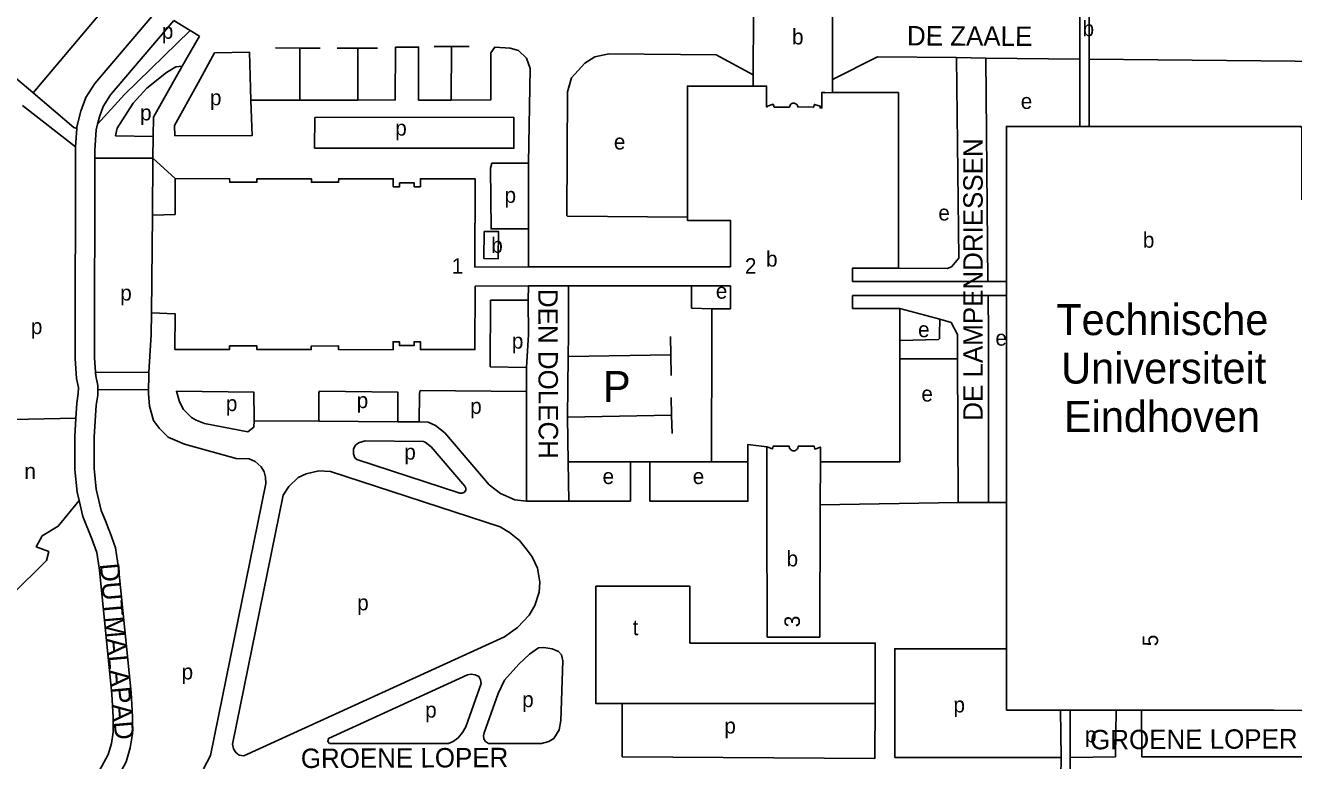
# Model space of a CAD drawing. Extents: x 161494 to 163033, y 383688 to 384862.
# Drawn here: x 161678.1 to 162005.1, y 384190.1 to 384379.7 of the extents above; entities that cross this region are included whole.
import ezdxf

# ---------------------------------------------------------------- set-up
doc = ezdxf.new("R2010")
doc.units = 0
for name, color, linetype in [('BLT_Basislijn', 7, 'Continuous'), ('BLT_Bebouwing', 7, 'Continuous'), ('BLT_Bebouwing_beschrifting', 7, 'Continuous'), ('BLT_Centroide', 7, 'Continuous'), ('BLT_Huisnummer', 7, 'Continuous'), ('BLT_Huisnummer_reeks', 7, 'Continuous'), ('BLT_Onderdoorgang_en_onderverdeling', 7, 'Continuous'), ('BLT_Onderverdeling_panden', 7, 'Continuous'), ('BLT_Straatnaam', 7, 'Continuous'), ('BLT_Tekst_parkeren', 7, 'Continuous'), ('BLT_Vlakafsluiter', 7, 'Continuous')]:
    doc.layers.add(name, color=color, linetype=linetype)

msp = doc.modelspace()

# ---------------------------------------------------------------- linework, layer by layer
at = {"layer": 'BLT_Basislijn'}
for p, q in [((161716.45, 384405.5), (161680.09, 384362.34)), ((161720.58, 384378.35), (161716.39, 384380.97)), ((161722.94, 384376.88), (161718.53, 384369.19)), ((161722.94, 384376.88), (161720.58, 384378.35)), ((161742.6, 384373.87), (161748.86, 384373.84)), ((161748.81, 384360.44), (161748.86, 384373.84)), ((161748.86, 384373.84), (161754.12, 384373.82)), ((161758.47, 384373.83), (161763.83, 384373.84)), ((161763.77, 384360.45), (161763.83, 384373.84)), ((161763.83, 384373.84), (161768.88, 384373.85)), ((161783.45, 384374.24), (161787.97, 384374.24)), ((161787.92, 384360.45), (161787.97, 384374.24)), ((161787.97, 384374.24), (161792.53, 384374.24)), ((161680, 384362.41), (161668.71, 384371.89)), ((161680.09, 384362.34), (161680, 384362.41)), ((161736.23, 384360.43), (161748.81, 384360.44)), ((161736.23, 384360.43), (161736.38, 384355.78)), ((161748.81, 384360.44), (161763.77, 384360.45)), ((161691.03, 384348.41), (161677.29, 384359)), ((161752.65, 384348.06), (161752.71, 384355.94)), ((161752.71, 384355.94), (161804.08, 384355.98)), ((161711, 384351.07), (161710.95, 384345.48)), ((161807.78, 384317.44), (161807.79, 384327.23)), ((161807.77, 384308.87), (161807.78, 384312.53)), ((161844.45, 384299.45), (161844.54, 384294.72)), ((161818.05, 384294.34), (161844.54, 384294.72)), ((161844.54, 384294.72), (161844.64, 384289.42)), ((161807.28, 384285.31), (161807.28, 384291.5)), ((161818.05, 384294.34), (161817.85, 384278.65)), ((161709.84, 384284.72), (161709.91, 384290.2)), ((161844.64, 384283.74), (161844.74, 384279.19)), ((161664.61, 384277.82), (161691.09, 384278.37)), ((161844.74, 384279.19), (161817.85, 384278.65)), ((161817.85, 384278.65), (161818.05, 384267.12)), ((161844.74, 384279.19), (161844.83, 384274.46)), ((161737.06, 384277.74), (161753.74, 384277.62)), ((161753.74, 384277.62), (161774.12, 384277.47)), ((161774.12, 384277.47), (161779.62, 384277.42)), ((161779.62, 384277.42), (161781.94, 384277.41)), ((161765.7, 384272.53), (161780.74, 384272.42)), ((161818.05, 384267.12), (161818.22, 384256.97)), ((161834.1, 384267.12), (161818.05, 384267.12)), ((161834.1, 384267.12), (161834.1, 384256.97)), ((161839.1, 384267.12), (161834.1, 384267.12)), ((161855.02, 384267.12), (161839.1, 384267.12)), ((161839.1, 384267.12), (161839.1, 384256.97)), ((161807.28, 384256.99), (161818.22, 384256.97)), ((161918.67, 384256.61), (161883.02, 384256.01)), ((161926.44, 384256.65), (161918.67, 384256.61)), ((161926.44, 384256.65), (161931.1, 384256.65)), ((161816.68, 384215.81), (161816.18, 384200.41)), ((161791.63, 384198.84), (161795.61, 384209.98)), ((161959.39, 384203.08), (161959.22, 384191.07)), ((161965.95, 384203.08), (161965.96, 384191.05)), ((161959.22, 384191.07), (161947.49, 384190.91)), ((161965.96, 384191.05), (162029.59, 384191.05))]:
    msp.add_line(p, q, dxfattribs=at)
for points in [[(161784.52, 384463.24), (161776.84, 384458.17), (161773.19, 384455.17), (161769.45, 384451.16), (161696.02, 384364.72), (161693.68, 384361.06), (161692.37, 384357.61), (161691.36, 384353.54), (161691.33, 384353.08)], [(161716.39, 384380.97), (161700.05, 384361.74), (161698.17, 384358.8), (161697.15, 384356.12), (161696.67, 384354.18)], [(161720.58, 384378.35), (161703.63, 384361.86), (161696.67, 384354.18)], [(161763.77, 384360.45), (161773.45, 384360.46), (161773.53, 384374.06), (161779.48, 384374.09), (161779.46, 384360.43), (161787.92, 384360.45)], [(161787.92, 384360.45), (161798.1, 384360.48), (161798.1, 384372.63), (161799.11, 384374.07), (161803.08, 384373.8), (161805.28, 384373.2), (161807.27, 384371.2), (161808.27, 384368.61), (161807.78, 384344.16)], [(161722.65, 384364.9), (161726.86, 384372.6), (161735.84, 384372.8), (161736.23, 384360.43)], [(161865.76, 384366.98), (161856.19, 384372.12), (161828.52, 384372.35), (161824.96, 384371.56), (161822.33, 384369.97), (161818.92, 384366.15), (161817.84, 384362.55), (161817.74, 384330.69), (161817.9, 384330.49), (161848.84, 384330.26)], [(161897.79, 384371.62), (161886.19, 384365.72)], [(161918.21, 384371.37), (161897.79, 384371.62)], [(161903.2, 384317.08), (161915.76, 384316.98), (161916.88, 384317.43), (161918.78, 384319.62), (161918.21, 384371.37)], [(161925.77, 384371.28), (161918.21, 384371.37)], [(161925.77, 384371.28), (161926.31, 384313.65)], [(161950, 384370.98), (161925.77, 384371.28)], [(162014.35, 384370.42), (161952.43, 384370.98)], [(161711, 384351.07), (161701.34, 384351.22), (161701.72, 384353.21), (161705.86, 384359.63), (161709.36, 384363.54), (161714.44, 384367.57), (161716.88, 384368.99), (161718.53, 384369.19)], [(161718.53, 384369.19), (161711.11, 384355.98), (161711, 384351.07)], [(161716.61, 384351.21), (161716.51, 384353.84), (161722.65, 384364.9)], [(161691.33, 384353.08), (161690.59, 384353.39), (161680.09, 384362.34)], [(161696.67, 384354.18), (161696.32, 384352.77), (161695.98, 384347.5), (161695.98, 384345.43)], [(161716.61, 384351.21), (161736.59, 384351.32), (161736.38, 384355.78)], [(161752.65, 384348.06), (161804.05, 384348.02), (161804.08, 384355.98)], [(161691.33, 384353.08), (161691.03, 384348.41)], [(161691.03, 384348.41), (161690.98, 384347.66), (161690.88, 384293.82), (161691.24, 384288.6), (161691.74, 384286.33), (161691.72, 384284.75), (161691.33, 384282.27), (161691.09, 384278.37)], [(161695.98, 384345.43), (161695.88, 384293.98), (161696.13, 384290.29)], [(161710.95, 384345.48), (161695.98, 384345.43)], [(161710.95, 384345.48), (161710.82, 384330.73)], [(161807.78, 384344.16), (161798.4, 384344.16), (161797.99, 384342.87), (161798.18, 384327.19), (161807.79, 384327.23)], [(161807.79, 384327.23), (161807.78, 384344.16)], [(161818.17, 384312.53), (161818.12, 384300), (161818.05, 384294.34)], [(161855.12, 384306.6), (161849.88, 384306.78), (161849.83, 384312.53)], [(161807.77, 384308.87), (161798.06, 384308.8), (161797.96, 384291.68), (161807.28, 384291.5)], [(161807.28, 384291.5), (161807.78, 384300), (161807.77, 384308.87)], [(161926.35, 384310.03), (161926.44, 384300), (161926.44, 384256.65)], [(161710.59, 384305.59), (161710.53, 384300), (161709.91, 384290.2)], [(161913.92, 384303.93), (161903.59, 384306.7)], [(161903.59, 384298.47), (161913.52, 384298.72), (161913.84, 384298.91), (161913.85, 384300), (161913.92, 384303.93)], [(161913.92, 384303.93), (161916.79, 384303.05), (161918.46, 384300), (161918.48, 384293.66)], [(161918.48, 384293.66), (161903.59, 384293.73)], [(161918.67, 384256.61), (161918.48, 384293.66)], [(161696.13, 384290.29), (161709.91, 384290.2)], [(161696.13, 384290.29), (161696.2, 384289.31), (161696.74, 384286.85), (161696.73, 384285.78)], [(161696.73, 384285.78), (161696.72, 384284.33), (161696.31, 384281.73), (161695.81, 384273.56), (161695.8, 384265.39), (161696.34, 384260.12), (161697.64, 384254.57), (161698.72, 384251.88)], [(161696.73, 384285.78), (161709.88, 384285.7)], [(161737.06, 384277.74), (161737.08, 384278.07), (161736.98, 384285.14), (161717, 384285.33), (161717.78, 384282.58), (161718.85, 384280.62), (161720.93, 384278.57), (161722.09, 384277.88), (161724.23, 384277.01), (161735.45, 384274.91), (161736.95, 384276.07), (161737.06, 384277.74)], [(161774.12, 384277.47), (161774.11, 384285.13), (161753.9, 384285.32), (161753.71, 384284.95), (161753.74, 384277.62)], [(161779.62, 384277.42), (161779.7, 384284.8), (161779.91, 384285.53), (161807.28, 384285.31)], [(161807.28, 384285.31), (161807.28, 384256.99)], [(161709.84, 384284.72), (161710.04, 384281.52), (161711.08, 384277.78), (161712.54, 384275.83), (161714.91, 384273.47), (161719.11, 384271.68), (161732.43, 384267.99)], [(161691.09, 384278.37), (161690.81, 384273.71), (161690.8, 384265.13), (161691.4, 384259.3), (161691.9, 384257.18)], [(161797.68, 384261.18), (161786.21, 384274.6), (161783.82, 384276.47), (161781.94, 384277.41)], [(161765.7, 384272.53), (161763.98, 384272.06), (161763.09, 384271.39), (161762.65, 384270.42), (161762.65, 384269.22), (161763.02, 384268.19), (161763.52, 384267.73), (161790.11, 384259.03), (161790.75, 384259.03), (161791.33, 384259.32), (161791.62, 384259.85), (161791.62, 384260.38), (161791.38, 384260.85)], [(161791.38, 384260.85), (161782.73, 384270.98), (161781.14, 384272.22), (161780.74, 384272.42)], [(161738.88, 384265.84), (161739.65, 384264.55), (161740, 384263.17), (161740.1, 384261.53), (161725.81, 384191.4), (161724.04, 384187.99)], [(161738.88, 384265.84), (161737.33, 384267.22), (161735.77, 384267.89), (161732.43, 384267.99)], [(161839.1, 384256.97), (161864.41, 384256.97), (161864.41, 384267.11)], [(161748.46, 384263.11), (161746.01, 384260.79), (161744.58, 384258.5), (161731.5, 384194.32), (161731.71, 384193.15), (161732.31, 384192.17), (161733.21, 384191.51), (161734.41, 384191.32)], [(161748.46, 384263.11), (161750.47, 384264.04), (161753.73, 384264.79), (161756.79, 384264.67), (161800.51, 384250.37)], [(161807.28, 384256.99), (161804.26, 384257.36), (161800.61, 384258.94), (161797.68, 384261.18)], [(161691.9, 384257.18), (161686.54, 384250.54), (161682.39, 384248.02), (161680.87, 384245.24), (161684.08, 384244.03), (161683.48, 384241.66), (161665.34, 384223.84)], [(161691.9, 384257.18), (161692.86, 384253.06), (161695.17, 384247.3), (161696.47, 384243.72), (161697.16, 384239.21), (161700.34, 384207.24), (161700.71, 384201.3), (161700.69, 384197.4), (161700.24, 384194.47), (161699.44, 384191.68), (161694.82, 384183.03), (161689.31, 384173.35), (161687.96, 384170.1)], [(161818.22, 384256.97), (161834.1, 384256.97)], [(161699.7, 384249.42), (161699.84, 384249.09), (161701.34, 384244.97), (161702.12, 384239.83), (161705.33, 384207.64), (161705.71, 384201.44), (161705.69, 384197.01), (161705.13, 384193.39), (161704.1, 384189.8), (161699.2, 384180.62), (161695.06, 384173.34)], [(161698.72, 384251.88), (161699.7, 384249.42)], [(161734.41, 384191.32), (161801.59, 384222.01), (161804.99, 384224.43), (161808, 384227.59), (161809.45, 384230.05), (161810.54, 384233.51), (161810.77, 384236.11), (161810.11, 384239.75), (161808.73, 384242.68), (161807.22, 384244.69), (161805.48, 384246.84), (161802.95, 384248.92), (161800.51, 384250.37)], [(161897.26, 384204.81), (161897.26, 384220.39), (161849.47, 384220.39), (161849.47, 384235.05), (161825.21, 384235.05), (161825.21, 384204.81), (161831.99, 384204.81)], [(161796.38, 384197.27), (161800, 384207.43), (161801.67, 384210.85), (161805.34, 384214.93), (161808.06, 384217.56), (161810.39, 384219.14), (161811.8, 384219.23), (161813.96, 384218.89), (161815.6, 384218.21), (161816.29, 384217.33), (161816.68, 384215.81)], [(161945.19, 384190.91), (161902.26, 384190.91), (161902.26, 384199.81), (161902.26, 384218.95), (161931.1, 384218.95)], [(161756.06, 384195.01), (161756.24, 384195.79), (161792.1, 384212.17), (161793.07, 384212.39), (161794.08, 384212.21), (161795.03, 384211.75), (161795.46, 384210.92), (161795.61, 384209.98)], [(161831.99, 384204.81), (161897.26, 384204.81)], [(161831.99, 384204.81), (161831.99, 384191.07), (161897.17, 384190.65), (161897.26, 384204.81)], [(161816.18, 384200.41), (161815.73, 384198.01), (161814.36, 384195.81), (161813.04, 384195.05), (161811.15, 384194.5), (161797.5, 384194.5), (161796.73, 384195.03), (161796.3, 384195.73), (161796.19, 384196.44), (161796.38, 384197.27)], [(161791.63, 384198.84), (161790.82, 384197.36), (161789.67, 384195.96), (161788.35, 384195), (161787.16, 384194.5), (161756.51, 384194.5), (161756.06, 384195.01)]]:
    msp.add_lwpolyline(points, dxfattribs=at)
at = {"layer": 'BLT_Bebouwing'}
for p, q in [((161865.85, 384382.45), (161865.76, 384366.98)), ((161886.19, 384365.72), (161886.18, 384382.29)), ((161950, 384381.82), (161950, 384370.98)), ((161952.4, 384381.83), (161952.43, 384370.98)), ((161950.02, 384353.63), (161950, 384370.98)), ((161952.43, 384370.98), (161952.43, 384353.63)), ((161865.76, 384366.98), (161865.75, 384364.03)), ((161886.19, 384362.35), (161886.19, 384365.72)), ((161975.98, 384353.62), (161970.72, 384353.62)), ((161807.78, 384317.44), (161794.02, 384317.32)), ((161859.89, 384317.39), (161807.78, 384317.44)), ((161794.08, 384312.41), (161807.78, 384312.53)), ((161807.78, 384312.53), (161818.17, 384312.53)), ((161818.17, 384312.53), (161849.83, 384312.53)), ((161849.83, 384312.53), (161859.89, 384312.53)), ((161903.59, 384293.73), (161903.59, 384298.47)), ((161869.31, 384270.97), (161869.32, 384255.99)), ((161883.02, 384256.01), (161883.09, 384267.12)), ((161869.32, 384255.99), (161869.32, 384254.95)), ((161882.96, 384221.92), (161883.02, 384255.35)), ((161883.02, 384255.35), (161883.02, 384256.01)), ((161869.32, 384254.95), (161869.34, 384221.93)), ((161869.34, 384221.93), (161882.96, 384221.92)), ((161945.19, 384190.91), (161945.14, 384185.91)), ((161947.49, 384190.91), (161947.49, 384185.91))]:
    msp.add_line(p, q, dxfattribs=at)
for points in [[(161848.84, 384330.26), (161848.82, 384364.03), (161865.75, 384364.03)], [(161886.19, 384362.35), (161903.2, 384362.37), (161903.2, 384317.08)], [(161931.1, 384313.65), (161931.08, 384353.63), (161950.02, 384353.63)], [(161952.43, 384353.63), (161970.72, 384353.62)], [(161975.98, 384353.62), (162000, 384353.62), (162007.04, 384353.64), (162007.04, 384353.41), (162007.27, 384353.41), (162007.26, 384334.69)], [(161710.82, 384330.73), (161716.67, 384330.95), (161716.68, 384340.21)], [(161716.68, 384340.21), (161730.74, 384340.15), (161730.76, 384339.24), (161737.79, 384339.24), (161737.79, 384340.14), (161751.82, 384340.14), (161751.82, 384339.26), (161758.86, 384339.23), (161758.87, 384340.14), (161772.93, 384340.13), (161772.93, 384338.06), (161774.56, 384338.06), (161774.56, 384339.06), (161778.33, 384339.06), (161778.33, 384338.06), (161779.96, 384338.06), (161779.96, 384340.13), (161794.05, 384340.15), (161794.02, 384317.32)], [(161710.82, 384330.73), (161710.59, 384305.59)], [(161848.84, 384330.26), (161848.84, 384329.38), (161859.9, 384329.38), (161859.89, 384317.39)], [(161796.41, 384326.55), (161800.11, 384326.52), (161800.03, 384319.51), (161796.34, 384319.54), (161796.41, 384326.55)], [(161891.4, 384313.66), (161891.4, 384317.1), (161903.2, 384317.08)], [(161794.08, 384312.41), (161794.01, 384296.08), (161779.94, 384296.07), (161779.93, 384298.1), (161778.3, 384298.11), (161778.3, 384297.11), (161774.54, 384297.11), (161774.54, 384298.11), (161772.91, 384298.11), (161772.89, 384296.06), (161758.85, 384296.08), (161758.84, 384297.01), (161751.81, 384296.98), (161751.81, 384296.08), (161737.77, 384296.1), (161737.77, 384297.01), (161730.73, 384297.01), (161730.74, 384296.11), (161716.64, 384296.08), (161716.67, 384305.34), (161710.59, 384305.59)], [(161859.89, 384312.53), (161859.88, 384306.59), (161855.12, 384306.6)], [(161891.4, 384313.66), (161926.31, 384313.65)], [(161931.1, 384313.65), (161926.31, 384313.65)], [(161891.39, 384310.03), (161926.35, 384310.03)], [(161903.59, 384306.7), (161891.39, 384306.7), (161891.39, 384310.03)], [(161926.35, 384310.03), (161931.1, 384310.03)], [(161931.1, 384256.65), (161931.09, 384300), (161931.1, 384310.03)], [(161855.12, 384306.6), (161855.11, 384300), (161855.02, 384267.12)], [(161903.59, 384306.7), (161903.59, 384298.47)], [(161903.59, 384293.73), (161903.57, 384267.1), (161883.09, 384267.12)], [(161869.31, 384270.97), (161864.42, 384271.65), (161864.41, 384267.11)], [(161864.41, 384267.11), (161855.02, 384267.12)], [(161931.1, 384218.95), (161931.1, 384250), (161931.1, 384256.65)], [(161931.1, 384203.07), (161931.1, 384218.95)], [(161931.1, 384203.07), (161945.03, 384203.07)], [(161945.03, 384203.07), (161945.19, 384190.91)], [(161947.5, 384203.08), (161947.49, 384190.91)], [(161947.5, 384203.08), (161959.39, 384203.08)], [(161959.39, 384203.08), (161965.95, 384203.08)], [(161965.95, 384203.08), (162000, 384203.09), (162007.29, 384203.04)]]:
    msp.add_lwpolyline(points, dxfattribs=at)
at = {"layer": 'BLT_Onderdoorgang_en_onderverdeling'}
msp.add_line((161931.1, 384313.65), (161931.1, 384310.03), dxfattribs=at)
for points in [[(161886.19, 384362.35), (161884.18, 384362.34), (161884.18, 384362.39), (161883.48, 384362.4), (161883.48, 384358.39), (161883, 384358.39), (161883, 384358.89), (161881.56, 384359.31), (161881.34, 384358.56), (161880.04, 384358.66), (161877.28, 384358.61), (161877.26, 384358.81), (161877.2, 384359), (161877.08, 384359.19), (161876.9, 384359.37), (161876.71, 384359.5), (161876.46, 384359.6), (161876.2, 384359.63), (161875.99, 384359.6), (161875.77, 384359.54), (161875.56, 384359.42), (161875.41, 384359.29), (161875.28, 384359.11), (161875.18, 384358.89), (161875.12, 384358.61), (161871.18, 384358.64), (161870.9, 384359.36), (161869.42, 384358.87), (161869.4, 384358.65), (161869.23, 384358.65), (161869.23, 384364.03), (161865.75, 384364.03)], [(161869.31, 384270.97), (161870.75, 384270.5), (161870.95, 384271.22), (161875.02, 384271.21), (161875.04, 384270.95), (161875.11, 384270.72), (161875.24, 384270.49), (161875.38, 384270.32), (161875.55, 384270.19), (161875.74, 384270.08), (161875.97, 384270.01), (161876.21, 384269.99), (161876.45, 384270.01), (161876.7, 384270.09), (161876.89, 384270.2), (161877.06, 384270.34), (161877.21, 384270.52), (161877.32, 384270.72), (161877.39, 384270.95), (161877.42, 384271.21), (161881.49, 384271.2), (161881.65, 384270.44), (161883.11, 384270.93), (161883.09, 384267.12)]]:
    msp.add_lwpolyline(points, dxfattribs=at)
at = {"layer": 'BLT_Onderverdeling_panden'}
for p, q in [((161950.02, 384353.63), (161952.43, 384353.63)), ((161945.03, 384203.07), (161947.5, 384203.08))]:
    msp.add_line(p, q, dxfattribs=at)
at = {"layer": 'BLT_Vlakafsluiter'}
msp.add_line((161716.68, 384340.21), (161710.95, 384345.48), dxfattribs=at)

# ---------------------------------------------------------------- texts
at = {"layer": 'BLT_Bebouwing_beschrifting'}
for s, p in [('Technische', (161943.93, 384299.82)), ('Universiteit', (161945.18, 384287.32)), ('Eindhoven', (161945.9, 384274.82))]:
    msp.add_text(s, height=8, dxfattribs=at).set_placement(p)
at = {"layer": 'BLT_Centroide'}
for s, p in [('b', (161950.71, 384376.9)), ('p', (161713.26, 384376.24)), ('b', (161875.78, 384374.77)), ('p', (161725.67, 384359.09)), ('e', (161934.77, 384358.15)), ('p', (161707.65, 384355.19)), ('p', (161773.45, 384351.26)), ('e', (161829.84, 384347.68)), ('p', (161801.64, 384333.92)), ('e', (161913.52, 384329.37)), ('b', (161798.22, 384321.03)), ('b', (161966.26, 384322.36)), ('b', (161869.08, 384317.48)), ('p', (161702.53, 384308.72)), ('e', (161856.13, 384309.21)), ('p', (161679.49, 384300.07)), ('e', (161908.29, 384299.28)), ('p', (161803.53, 384296.33)), ('e', (161928.23, 384297.1)), ('e', (161909.15, 384282.69)), ('p', (161729.77, 384280.22)), ('p', (161763.51, 384281)), ('p', (161792.78, 384279.52)), ('p', (161775.79, 384267.7)), ('n', (161677.81, 384262.75)), ('e', (161826.92, 384261.41)), ('e', (161850.17, 384261.41)), ('b', (161874.38, 384240.18)), ('p', (161763.64, 384228.84)), ('t', (161834.69, 384222.43)), ('p', (161718.36, 384211.01)), ('p', (161806.19, 384203.87)), ('p', (161781.16, 384201.18)), ('p', (161917.41, 384202.51)), ('p', (161858.32, 384197.07)), ('p', (161951.34, 384194.8))]:
    msp.add_text(s, height=4, dxfattribs=at).set_placement(p)
at = {"layer": 'BLT_Huisnummer'}
for s, p in [('3', (161877.82, 384224.48)), ('5', (161970.19, 384219.58))]:
    msp.add_text(s, height=4, rotation=90.1214, dxfattribs=at).set_placement(p)
at = {"layer": 'BLT_Huisnummer_reeks'}
for s, p in [('1', (161788.01, 384315.65)), ('2', (161863.64, 384315.65))]:
    msp.add_text(s, height=4, rotation=0.1214, dxfattribs=at).set_placement(p)
at = {"layer": 'BLT_Straatnaam'}
for s, rotation, p in [('DE ZAALE', 359.7394, (161905.42, 384374.53)), ('DE LAMPENDRIESSEN', 89.9848, (161924.94, 384277.74)), ('DEN DOLECH', 270.1614, (161810.34, 384311.72)), ('DUTMALAPAD', 275, (161697.27, 384240.8)), ('GROENE LOPER', 0.2472, (161952.67, 384192.99)), ('GROENE LOPER', 0.2472, (161749.12, 384188.17))]:
    msp.add_text(s, height=5, rotation=rotation, dxfattribs=at).set_placement(p)
at = {"layer": 'BLT_Tekst_parkeren'}
msp.add_text('P', height=8, dxfattribs=at).set_placement((161827.03, 384282.55))

doc.saveas('drawing.dxf')
